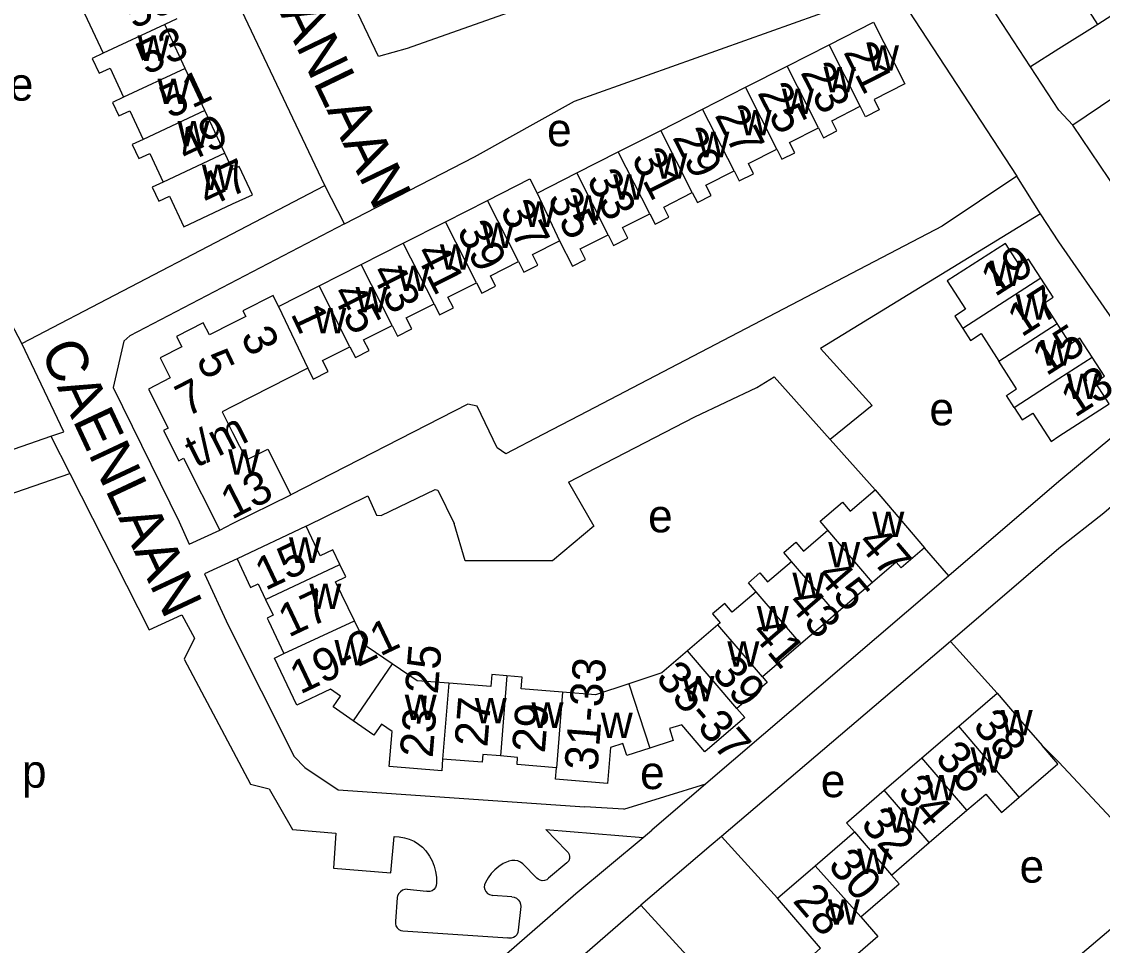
# Model space of a CAD drawing. Extents: x 157768 to 159790, y 387230 to 389604.
# Drawn here: x 158974.5 to 159105.3, y 388960.7 to 389072.5 of the extents above; entities that cross this region are included whole.
import ezdxf

# ---------------------------------------------------------------- set-up
doc = ezdxf.new("R2010")
doc.units = 0
for name, color, linetype in [('BLT_Basislijn', 7, 'Continuous'), ('BLT_Bebouwing', 7, 'Continuous'), ('BLT_Centroide', 7, 'Continuous'), ('BLT_Huisnummer', 7, 'Continuous'), ('BLT_Huisnummer_ tussenligend', 7, 'Continuous'), ('BLT_Huisnummer_reeks', 7, 'Continuous'), ('BLT_Onderverdeling_panden', 7, 'Continuous'), ('BLT_Straatnaam', 7, 'Continuous')]:
    doc.layers.add(name, color=color, linetype=linetype)

msp = doc.modelspace()

# ---------------------------------------------------------------- linework, layer by layer
at = {"layer": 'BLT_Basislijn'}
for p, q in [((159011.16, 389052.69), (158991.47, 389094.13)), ((159096.55, 389067.06), (159082.73, 389088.2)), ((159119.8, 389033.05), (159101.7, 389059.99)), ((159097.78, 389049.25), (159094.89, 389053.84)), ((158974.48, 389033.56), (159011.16, 389052.69)), ((159013.53, 389048.04), (159011.16, 389052.69)), ((159097.78, 389049.25), (159071.13, 389032.96)), ((158979.58, 389022.9), (158974.48, 389033.56)), ((159065.54, 389029.54), (159072.31, 389021.95)), ((159041.96, 389024.86), (159037.53, 389022.55)), ((158971.87, 389020.23), (158978.01, 389022.36)), ((158978.01, 389022.36), (158979.58, 389022.9)), ((158978.01, 389022.36), (158980.29, 389017.86)), ((159072.31, 389021.95), (159077.75, 389015.86)), ((158939.61, 389003.75), (158980.29, 389017.86)), ((159086.68, 389005.44), (159083.75, 389008.86)), ((159086.88, 388997.5), (159059.18, 388973.93)), ((159086.88, 388997.5), (159092.51, 388991.26)), ((159047.36, 388977.22), (159057.27, 388980.27)), ((159057.27, 388980.27), (159050.75, 388974.69)), ((159047.36, 388977.22), (159042.61, 388977.51)), ((159037.92, 388974.74), (159049.7, 388973.81)), ((159040.39, 388972.16), (159037.92, 388974.74)), ((159049.7, 388973.81), (159050.75, 388974.69)), ((159065.96, 388966.45), (159059.18, 388973.93)), ((159041.53, 388967.02), (159049.7, 388973.81)), ((159036.83, 388968.88), (159035.13, 388970.59)), ((159040.43, 388970.71), (159038.24, 388968.85)), ((159021.13, 388967.52), (159023.46, 388967.28)), ((159019.93, 388966.54), (159019.72, 388963.64)), ((159033.78, 388966.59), (159031.48, 388966.79)), ((159034.87, 388965.45), (159034.55, 388962.56)), ((159020.6, 388962.48), (159033.31, 388961.63))]:
    msp.add_line(p, q, dxfattribs=at)
for points in [[(159081.66, 389089.89), (159079.88, 389089.71), (159055.96, 389081.61), (159021.14, 389069.28), (159017.64, 389068.31), (159003.42, 389098.2), (159002.51, 389099.58), (159002.31, 389103.56), (159002.73, 389104.71), (159004.65, 389106.84), (159024.78, 389114.04), (159028.26, 389115.03)], [(159125.64, 389089.31), (159131.74, 389093.33), (159132.61, 389093.3), (159136.29, 389089.7), (159136.29, 389089.06), (159135.54, 389088.11), (159113.21, 389067.8), (159101.7, 389059.99)], [(159013.53, 389048.04), (159029.29, 389056.16), (159041.36, 389062.9), (159079.64, 389076.59), (159080.37, 389076.04), (159094.89, 389053.84)], [(159104.72, 389072.18), (159100, 389069.25), (159096.55, 389067.06)], [(159101.7, 389059.99), (159100, 389061.81), (159096.55, 389067.06)], [(158974.48, 389033.56), (158971.43, 389039.34), (158962.39, 389058.6), (158961.59, 389058.76), (158955.2, 389055.7)], [(159094.89, 389053.84), (159085.88, 389047.78), (159041.96, 389024.86)], [(159113.3, 389027.94), (159106.49, 389036.51), (159100, 389045.88), (159097.78, 389049.25)], [(159013.53, 389048.04), (158987.55, 389034.5), (158986.82, 389033.85), (158985.54, 389028.26), (158993.54, 389011.98), (158994.72, 389009.27), (158998.47, 389011)], [(159071.13, 389032.96), (159077.4, 389026.06), (159072.31, 389021.95)], [(159045.1, 389019.08), (159055.94, 389024.68), (159063.43, 389028.26), (159065.54, 389029.54)], [(159113.3, 389027.94), (159100, 389016.89), (159086.68, 389005.44)], [(159037.53, 389022.55), (159033.08, 389020.23), (159032, 389020.95), (159029.58, 389025.98), (159028.46, 389026.24), (159007.05, 389015.27)], [(159117.14, 389023.24), (159112.14, 389018.83), (159105.44, 389013.04), (159100, 389008.76), (159086.88, 388997.5)], [(159040.65, 389016.79), (159045.1, 389019.08)], [(158980.29, 389017.86), (158989.89, 388998.92), (158993.85, 389000.75), (158995.4, 388997.93), (158994.13, 388995.38), (159002.18, 388980.26), (159004.44, 388979.7), (159007.26, 388974.75), (159012.49, 388974.33), (159012.21, 388970.09), (159019.13, 388969.52), (159019.55, 388973.9)], [(159008.89, 389011.47), (159016.38, 389015.12), (159017.41, 389012.8), (159017.98, 389012.77), (159024.52, 389015.9), (159024.83, 389015.82), (159026.81, 389011.81)], [(159040.65, 389016.79), (159043.72, 389011.47), (159038.7, 389007.28), (159028.14, 389007.28), (159026.81, 389011.81)], [(159000.54, 389007.51), (158996.6, 389005.68), (158999.45, 388999.47), (159007.46, 388983.61), (159008.73, 388982.27), (159012.78, 388979.55), (159042.61, 388977.51)], [(159086.68, 389005.44), (159084.9, 389003.92), (159057.27, 388980.27)], [(159113.26, 388968.72), (159100, 388982.91), (159097.96, 388984.93)], [(159019.55, 388973.9), (159020.17, 388973.88), (159020.79, 388973.77), (159021.38, 388973.59), (159021.95, 388973.33), (159022.48, 388973), (159022.96, 388972.61), (159023.39, 388972.16), (159023.75, 388971.65), (159023.81, 388971.55)], [(159059.18, 388973.93), (159057.91, 388972.85), (159049.42, 388965.59)], [(159023.81, 388971.55), (159024.14, 388970.96), (159024.39, 388970.33), (159024.56, 388969.68), (159024.66, 388969.01), (159024.67, 388968.26)], [(159040.39, 388972.16), (159040.59, 388971.98), (159040.72, 388971.75), (159040.78, 388971.49), (159040.76, 388971.23), (159040.67, 388970.98), (159040.43, 388970.71)], [(159033.33, 388970.89), (159032.76, 388970.63), (159032.22, 388970.29), (159031.73, 388969.89), (159031.29, 388969.43), (159030.92, 388968.92), (159030.59, 388968.34)], [(159035.13, 388970.59), (159034.84, 388970.8), (159034.5, 388970.95), (159034.15, 388971.02), (159033.78, 388971.02), (159033.43, 388970.93), (159033.33, 388970.89)], [(159038.24, 388968.85), (159038.02, 388968.68), (159037.76, 388968.58), (159037.48, 388968.56), (159037.21, 388968.62), (159036.96, 388968.75), (159036.83, 388968.88)], [(159021.13, 388967.52), (159020.83, 388967.5), (159020.55, 388967.4), (159020.3, 388967.23), (159020.1, 388967), (159019.97, 388966.73), (159019.93, 388966.54)], [(159024.67, 388968.26), (159024.64, 388967.99), (159024.54, 388967.73), (159024.36, 388967.51), (159024.13, 388967.35), (159023.87, 388967.27), (159023.59, 388967.26), (159023.46, 388967.28)], [(159030.59, 388968.34), (159030.49, 388968.07), (159030.46, 388967.79), (159030.51, 388967.5), (159030.64, 388967.24), (159030.84, 388967.03), (159031.08, 388966.88), (159031.36, 388966.8), (159031.48, 388966.79)], [(159011.32, 388939.97), (159031.27, 388958.11), (159041.53, 388967.02)], [(159033.78, 388966.59), (159034.07, 388966.55), (159034.34, 388966.43), (159034.57, 388966.24), (159034.74, 388965.99), (159034.84, 388965.71), (159034.87, 388965.45)], [(159021.4, 388940.88), (159030, 388948.75), (159049.42, 388965.59)], [(159049.42, 388965.59), (159075.43, 388937.12), (159077.24, 388935.3), (159072.95, 388931.73)], [(159109.47, 388965.41), (159085.11, 388944.75)], [(159019.72, 388963.64), (159019.71, 388963.36), (159019.77, 388963.09), (159019.91, 388962.85), (159020.11, 388962.66), (159020.35, 388962.53), (159020.6, 388962.48)], [(159034.55, 388962.56), (159034.51, 388962.28), (159034.39, 388962.03), (159034.21, 388961.82), (159033.98, 388961.68), (159033.71, 388961.6), (159033.43, 388961.6), (159033.31, 388961.63)]]:
    msp.add_lwpolyline(points, dxfattribs=at)
at = {"layer": 'BLT_Bebouwing'}
for p, q in [((159111.7, 389076.69), (159104.72, 389072.18)), ((158981.76, 389074.19), (158984.33, 389068.7)), ((158993.23, 389072.86), (158991.78, 389072.18)), ((158994.27, 389066.86), (158991.78, 389072.18)), ((159067.11, 389067.15), (159072.18, 389069.73)), ((158996.65, 389061.78), (158994.27, 389066.86)), ((159062.05, 389064.58), (159067.11, 389067.15)), ((159056.88, 389061.95), (159062.05, 389064.58)), ((158999.07, 389056.6), (158996.65, 389061.78)), ((159051.81, 389059.37), (159056.88, 389061.95)), ((159046.67, 389056.77), (159051.81, 389059.37)), ((159041.64, 389054.21), (159046.67, 389056.77)), ((159036.85, 389051.77), (159041.64, 389054.21)), ((159025.77, 389048.31), (159030.83, 389050.88)), ((159020.65, 389045.71), (159025.77, 389048.31)), ((159015.56, 389043.12), (159020.65, 389045.71)), ((159010.47, 389040.54), (159015.56, 389043.12)), ((159005.57, 389038.05), (159010.47, 389040.54)), ((159077.75, 389015.86), (159083.75, 389008.86)), ((159008.89, 389011.47), (159000.54, 389007.51)), ((159077.45, 389004.66), (159073.06, 389000.89)), ((159058.71, 388999.52), (159055.04, 388996.38)), ((159068.77, 388997.21), (159064.12, 388993.22)), ((159087.87, 388987.26), (159092.51, 388991.26)), ((159083.4, 388983.42), (159087.87, 388987.26)), ((159099.86, 388982.71), (159097.96, 388984.93)), ((159078.85, 388979.5), (159083.4, 388983.42)), ((159074.29, 388975.58), (159078.85, 388979.5)), ((159084.3, 388973.17), (159088.85, 388977.09)), ((159074.29, 388975.58), (159075.26, 388974.46)), ((159070.5, 388970.36), (159075.26, 388974.46)), ((159079.74, 388969.25), (159084.3, 388973.17)), ((159065.96, 388966.45), (159070.5, 388970.36))]:
    msp.add_line(p, q, dxfattribs=at)
for points in [[(159104.72, 389072.18), (159102.98, 389074.87), (159101.87, 389074.15), (159100.39, 389076.44)], [(159072.18, 389069.73), (159077.57, 389072.46), (159081.36, 389065.01), (159077.62, 389063.11), (159078.26, 389061.86), (159076.6, 389061.02), (159075.96, 389062.29)], [(158984.33, 389068.7), (158983.01, 389068.08), (158983.85, 389066.28), (158985.16, 389066.89), (158986.81, 389063.37)], [(158986.81, 389063.37), (158985.47, 389062.75), (158986.24, 389061.11), (158987.56, 389061.73), (158989.17, 389058.28)], [(159070.91, 389059.68), (159071.52, 389058.48), (159073.14, 389059.31), (159072.52, 389060.54), (159075.96, 389062.29)], [(159065.85, 389057.09), (159066.48, 389055.87), (159068.03, 389056.66), (159067.4, 389057.9), (159070.91, 389059.68)], [(158989.17, 389058.28), (158987.86, 389057.67), (158988.66, 389055.95), (158989.98, 389056.56), (158991.59, 389053.11)], [(158991.59, 389053.11), (158990.26, 389052.49), (158991.05, 389050.8), (158992.37, 389051.42), (158994.11, 389047.7), (159000, 389050.46), (159002.4, 389051.58), (159000.8, 389055), (159000, 389054.62), (158999.07, 389056.6)], [(159060.69, 389054.46), (159061.31, 389053.24), (159063.04, 389054.12), (159062.42, 389055.34), (159065.85, 389057.09)], [(159055.63, 389051.85), (159056.25, 389050.63), (159057.9, 389051.47), (159057.27, 389052.72), (159060.69, 389054.46)], [(159030.83, 389050.88), (159035.98, 389053.49), (159036.85, 389051.77)], [(159050.49, 389049.26), (159051.12, 389048.01), (159052.8, 389048.86), (159052.17, 389050.09), (159055.63, 389051.85)], [(159045.43, 389046.73), (159046.09, 389045.45), (159047.82, 389046.33), (159047.18, 389047.6), (159050.49, 389049.26)], [(159034.59, 389043.49), (159035.24, 389042.21), (159036.95, 389043.07), (159036.31, 389044.33), (159039.57, 389045.99)], [(159039.57, 389045.99), (159041.12, 389042.93), (159042.7, 389043.74), (159042.06, 389045.01), (159045.43, 389046.73)], [(159097.81, 389041.47), (159096.33, 389043.76), (159095.21, 389043.04), (159093.52, 389045.67), (159086.49, 389041.14), (159088.69, 389037.73), (159087.41, 389036.9), (159088.38, 389035.39)], [(159029.51, 389040.93), (159030.16, 389039.66), (159031.83, 389040.52), (159031.2, 389041.76), (159034.59, 389043.49)], [(159024.38, 389038.37), (159025.05, 389037.05), (159026.71, 389037.89), (159026.06, 389039.17), (159029.51, 389040.93)], [(159099.8, 389035.99), (159098.21, 389038.47), (159099.29, 389039.17), (159097.81, 389041.47)], [(159005.57, 389038.05), (159004.89, 389039.38), (159001.24, 389037.53), (159001.58, 389036.86), (159000, 389036.05), (158997.19, 389034.62), (158996.45, 389036.08), (158993.21, 389034.44), (158993.85, 389033.19), (158991.21, 389031.85), (158992.45, 389029.41), (158989.8, 389028.06), (158992.21, 389023.32), (158991.63, 389023.03), (158993.48, 389019.38), (158994.07, 389019.68), (158998.47, 389011)], [(159019.3, 389035.76), (159019.95, 389034.47), (159021.68, 389035.35), (159021.01, 389036.66), (159024.38, 389038.37)], [(159014.2, 389033.19), (159014.87, 389031.87), (159016.51, 389032.71), (159015.85, 389034.01), (159019.3, 389035.76)], [(159088.38, 389035.39), (159089.31, 389033.95), (159090.59, 389034.77), (159092.73, 389031.44)], [(159104.03, 389031.93), (159102.55, 389034.23), (159101.41, 389033.49), (159100, 389035.68), (159099.8, 389035.99)], [(159009.1, 389030.58), (159009.76, 389029.27), (159011.55, 389030.18), (159010.88, 389031.51), (159014.2, 389033.19)], [(159094.6, 389025.82), (159093.65, 389027.3), (159094.88, 389028.1), (159092.73, 389031.44)], [(159094.6, 389025.82), (159095.56, 389024.34), (159096.84, 389025.16), (159099.05, 389021.73), (159100, 389022.34), (159106.09, 389026.26), (159104.38, 389028.91), (159105.5, 389029.64), (159104.03, 389031.93)], [(159009.1, 389030.58), (159000, 389025.96), (158998.72, 389025.3), (159000, 389022.79), (159001.68, 389019.49), (159004.24, 389020.79), (159007.05, 389015.27)], [(159072.04, 389010.97), (159071.1, 389012.06), (159073.81, 389014.38), (159074.75, 389013.29), (159077.75, 389015.86)], [(158998.47, 389011), (159000, 389011.78), (159007.05, 389015.27)], [(159012.96, 389006.84), (159012.12, 389008.61), (159010.6, 389007.88), (159008.89, 389011.47)], [(159067.65, 389007.2), (159066.71, 389008.29), (159068.17, 389009.54), (159069.1, 389008.46), (159072.04, 389010.97)], [(159083.75, 389008.86), (159080.9, 389006.42), (159080.31, 389007.11), (159077.45, 389004.66)], [(159000.54, 389007.51), (159002.18, 389004.05), (159003.09, 389004.48), (159003.99, 389002.58)], [(159014.76, 389000), (159012.44, 389004.74), (159013.68, 389005.33), (159012.96, 389006.84)], [(159063.36, 389003.52), (159062.43, 389004.6), (159063.82, 389005.8), (159064.75, 389004.72), (159067.65, 389007.2)], [(159063.36, 389003.52), (159060.46, 389001.04), (159059.56, 389002.1), (159058.09, 389000.84), (159058.8, 389000), (159059, 388999.77), (159058.71, 388999.52)], [(159003.99, 389002.58), (159004.89, 389000.68), (159004.17, 389000.34), (159004.33, 389000), (159006.21, 388996.04)], [(159019.3, 388994.82), (159016.29, 388996.88), (159014.76, 389000)], [(159073.06, 389000.89), (159072.02, 389000), (159068.77, 388997.21)], [(159055.04, 388996.38), (159051.96, 388993.73), (159047.93, 388992.39)], [(159014.6, 388987.91), (159012.15, 388989.6), (159013.06, 388990.91), (159011.84, 388991.75), (159007.77, 388989.81), (159005.07, 388995.5), (159006.21, 388996.04)], [(159026.15, 388992.46), (159022.32, 388992.77), (159019.3, 388994.82)], [(159033.2, 388993.35), (159031.37, 388993.5), (159031.25, 388992.05), (159026.15, 388992.46)], [(159039.92, 388991.37), (159034.92, 388991.77), (159035.03, 388993.2), (159033.2, 388993.35)], [(159047.93, 388992.39), (159043.91, 388991.05), (159039.92, 388991.37)], [(159064.12, 388993.22), (159064.7, 388992.54), (159061.03, 388989.39)], [(159092.51, 388991.26), (159095.77, 388987.47), (159097.96, 388984.93)], [(159061.03, 388989.39), (159061.97, 388988.3), (159057.15, 388984.17), (159054.35, 388987.44), (159052.86, 388986.97), (159053.32, 388985.52), (159050.49, 388984.61)], [(159025.41, 388983.28), (159025.3, 388981.86), (159018.95, 388982.37), (159019.29, 388986.61), (159018, 388987.5), (159017.09, 388986.19), (159014.6, 388987.91)], [(159050.49, 388984.61), (159047.69, 388983.73), (159047.23, 388985.18), (159045.73, 388984.7), (159045.37, 388980.33), (159039.07, 388980.84), (159039.18, 388982.23)], [(159032.42, 388983.66), (159030.29, 388983.83), (159030.21, 388982.9), (159025.41, 388983.28)], [(159039.18, 388982.23), (159034.42, 388982.62), (159034.49, 388983.49), (159032.42, 388983.66)], [(159095.18, 388978.68), (159099.86, 388982.71)], [(159088.85, 388977.09), (159091.14, 388979.05), (159093.03, 388976.83), (159095.18, 388978.68)], [(159076.04, 388964.19), (159080.67, 388968.17), (159079.74, 388969.25)], [(159072.65, 388957.1), (159070.38, 388959.73), (159071.16, 388960.4), (159065.96, 388966.45)], [(159076.04, 388964.19), (159078.1, 388961.8), (159072.65, 388957.1)]]:
    msp.add_lwpolyline(points, dxfattribs=at)
at = {"layer": 'BLT_Onderverdeling_panden'}
for p, q in [((158991.78, 389072.18), (158984.33, 389068.7)), ((159075.96, 389062.29), (159072.18, 389069.73)), ((158994.27, 389066.86), (158986.81, 389063.37)), ((159070.91, 389059.68), (159067.11, 389067.15)), ((159065.85, 389057.09), (159062.05, 389064.58)), ((158996.65, 389061.78), (158989.17, 389058.28)), ((159060.69, 389054.46), (159056.88, 389061.95)), ((159055.63, 389051.85), (159051.81, 389059.37)), ((158999.07, 389056.6), (158991.59, 389053.11)), ((159050.49, 389049.26), (159046.67, 389056.77)), ((159045.43, 389046.73), (159041.64, 389054.21)), ((159036.85, 389051.77), (159039.57, 389045.99)), ((159034.59, 389043.49), (159030.83, 389050.88)), ((159029.51, 389040.93), (159025.77, 389048.31)), ((159024.38, 389038.37), (159020.65, 389045.71)), ((159019.3, 389035.76), (159015.56, 389043.12)), ((159014.2, 389033.19), (159010.47, 389040.54)), ((159097.81, 389041.47), (159088.38, 389035.39)), ((159005.57, 389038.05), (159009.1, 389030.58)), ((159092.73, 389031.44), (159099.8, 389035.99)), ((159077.45, 389004.66), (159072.04, 389010.97)), ((159003.99, 389002.58), (159012.96, 389006.84)), ((159073.06, 389000.89), (159067.65, 389007.2)), ((159068.77, 388997.21), (159063.36, 389003.52)), ((159006.21, 388996.04), (159014.76, 389000)), ((159064.12, 388993.22), (159058.71, 388999.52)), ((159061.03, 388989.39), (159055.04, 388996.38)), ((159019.3, 388994.82), (159014.6, 388987.91)), ((159026.15, 388992.46), (159025.41, 388983.28)), ((159033.2, 388993.35), (159032.42, 388983.66)), ((159047.93, 388992.39), (159050.49, 388984.61)), ((159039.92, 388991.37), (159039.18, 388982.23)), ((159095.18, 388978.68), (159087.87, 388987.26)), ((159088.85, 388977.09), (159083.4, 388983.42)), ((159084.3, 388973.17), (159078.85, 388979.5)), ((159075.26, 388974.46), (159079.74, 388969.25)), ((159070.5, 388970.36), (159076.04, 388964.19))]:
    msp.add_line(p, q, dxfattribs=at)
msp.add_lwpolyline([(159094.6, 389025.82), (159100, 389029.34), (159104.03, 389031.93)], dxfattribs=at)

# ---------------------------------------------------------------- texts
at = {"layer": 'BLT_Centroide'}
for s, p in [('w', (158988.5, 389067.78)), ('w', (159076.77, 389066.58)), ('w', (159071.53, 389063.95)), ('e', (158972.92, 389062.96)), ('w', (158990.91, 389062.56)), ('w', (159066.48, 389061.34)), ('w', (159061.36, 389058.75)), ('w', (158993.33, 389057.44)), ('e', (159038.05, 389057.45)), ('w', (159056.25, 389056.12)), ('w', (159051.16, 389053.53)), ('w', (158996.27, 389052.16)), ('w', (159046.06, 389050.98)), ('w', (159041.14, 389048.45)), ('w', (159035.2, 389047.69)), ('w', (159030.17, 389045.12)), ('w', (159025.08, 389042.52)), ('w', (159091.62, 389040.53)), ('w', (159019.97, 389039.92)), ('w', (159014.88, 389037.33)), ('w', (159094.77, 389036.44)), ('w', (159009.89, 389034.8)), ('w', (159097.76, 389030.91)), ('w', (159100.94, 389026.84)), ('e', (159084.33, 389023.67)), ('w', (158999.45, 389017.69)), ('e', (159050.28, 389010.72)), ('w', (159077.42, 389010.14)), ('w', (159006.82, 389007.03)), ('w', (159072.08, 389006.47)), ('w', (159067.75, 389002.75)), ('w', (159009.29, 389001.44)), ('w', (159063.44, 388998.73)), ('w', (159012.32, 388994.62)), ('w', (159059.88, 388994.45)), ('w', (159054.45, 388990.28)), ('w', (159020.83, 388988)), ('w', (159029.31, 388987.59)), ('w', (159036.17, 388987.06)), ('w', (159044.56, 388985.83)), ('w', (159092.95, 388986.14)), ('w', (159089.3, 388981.62)), ('p', (158974.5, 388979.82)), ('e', (159049.31, 388979.65)), ('e', (159071.18, 388978.67)), ('w', (159083.84, 388978.3)), ('w', (159079.3, 388974.38)), ('w', (159075.59, 388969.38)), ('e', (159095.24, 388968.33)), ('w', (159072.03, 388963.23))]:
    msp.add_text(s, height=4, dxfattribs=at).set_placement(p)
at = {"layer": 'BLT_Huisnummer'}
for s, rotation, p in [('55', 25.0538, (158988.02, 389071.58)), ('21', 296.9351, (159073.86, 389068.85)), ('51', 25.0538, (158992.38, 389060.72)), ('25', 296.9351, (159063.46, 389063.92)), ('29', 296.9351, (159053.18, 389058.52)), ('47', 25.06, (158997.03, 389049.98)), ('33', 296.9351, (159042.78, 389053.45)), ('37', 296.9351, (159032.29, 389049.74)), ('41', 296.9351, (159022, 389044.57)), ('19', 32.8093, (159092.26, 389039.15)), ('45', 296.9351, (159011.91, 389039.68)), ('1', 295.2805, (159006.97, 389037.18)), ('13', 32.8084, (159101.94, 389024.54)), ('47', 310.6304, (159075.47, 389009.38)), ('15', 25.3922, (159003.96, 389003.62)), ('43', 310.6252, (159067.02, 389002.1)), ('39', 310.6252, (159057.86, 388993.67)), ('27', 85.3836, (159030.82, 388984.66)), ('38', 310.7188, (159089.45, 388987.21)), ('32', 310.7351, (159075.89, 388975.33)), ('28', 310.7167, (159067.68, 388966.09))]:
    msp.add_text(s, height=4, rotation=rotation, dxfattribs=at).set_placement(p)
at = {"layer": 'BLT_Huisnummer_ tussenligend'}
for s, rotation, p in [('53', 25.0538, (158989.54, 389066.01)), ('23', 296.9351, (159068.67, 389066.38)), ('27', 296.9351, (159058.28, 389061.2)), ('49', 25.06, (158994.4, 389055.35)), ('31', 296.9351, (159048.2, 389056)), ('35', 296.9351, (159038.03, 389051.16)), ('39', 296.9351, (159027.07, 389047.23)), ('43', 296.9351, (159016.66, 389042.22)), ('17', 32.8084, (159095.48, 389034.27)), ('15', 32.8084, (159098.48, 389029.57)), ('45', 310.6252, (159070.54, 389005.36)), ('17', 25.3922, (159006.77, 388997.95)), ('41', 310.6252, (159062.61, 388998.48)), ('29', 85.3817, (159037.78, 388983.94)), ('36', 310.7351, (159084.89, 388983.33)), ('34', 310.7351, (159080.34, 388979.28)), ('30', 310.7167, (159071.92, 388970.34))]:
    msp.add_text(s, height=4, rotation=rotation, dxfattribs=at).set_placement(p)
at = {"layer": 'BLT_Huisnummer_reeks'}
for s, rotation, p in [('3', 295.2805, (159000.92, 389034.5)), ('5', 295.2805, (158995.54, 389031.68)), ('7', 26.9316, (158994.43, 389024.62)), ('t/m', 26.9316, (158995.56, 389018.48)), ('13', 26.9316, (158999.89, 389012.22)), ('19-21', 25.3922, (159008.17, 388991.07)), ('23-25', 85.3836, (159024.2, 388983.36)), ('31-33', 85.3948, (159044.13, 388981.77)), ('35-37', 310.6172, (159051.07, 388993))]:
    msp.add_text(s, height=4, rotation=rotation, dxfattribs=at).set_placement(p)
at = {"layer": 'BLT_Straatnaam'}
for s, height, rotation, p in [('ARGENTANLAAN', 4.9999, 295.7576, (158993.56, 389098.67)), ('CAENLAAN', 5, 295.1063, (158976.65, 389032.7))]:
    msp.add_text(s, height=height, rotation=rotation, dxfattribs=at).set_placement(p)

doc.saveas('drawing.dxf')
